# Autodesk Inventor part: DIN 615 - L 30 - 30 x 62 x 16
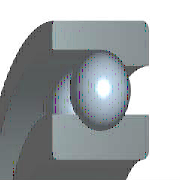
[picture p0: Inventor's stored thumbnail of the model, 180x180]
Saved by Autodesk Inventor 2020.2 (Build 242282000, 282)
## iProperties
Manager: www.cadconsulting.pl
Company: Fabian Stasiak CAD Consulting
Created: 2010-02
Part Number: DIN 615 - L 30 - 30 x 62 x 16
Material: Stal, miękka
Description: Łożysko kulkowe
Document SubType Name: Modeling
Standard: DIN 615
Designer: F.Stasiak
Standards Organization: DIN
Language: pl-PL
Size Designation: L 30 - 30 x 62 x 16
Categories: <MemberInstance><Categories><Category DisplayName="Części wałów" InternalName="7f7aeb1f-a693-4053-b835-cee3144e0d98" Mnemonic="SHFT"><Category DisplayName="Łoży
Density: 1 g/cm^3
Appearance: Metal-Stal
IsCustomPart: 0
Author: F.Stasiak
Subject: Zbiór ćwiczeń. Autodesk Inventor 2020. Kurs podstawowy
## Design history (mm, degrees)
sketch "Sketch" dims "d4" = 9.28 (= DDB)
  geometry: L1 (3.36, 23)-(12.64, 23); L2 (4.288, 20.216)-(0, 20.216); L3 (11.712, 20.216)-(16, 20.216); L4 (8, 27.64)-(0, 27.64); L5 (0, 31)-(16, 31); L6 (0, 15)-(16, 15); L7 (16, 15)-(16, 20.216); L8 (11.712, 25.784)-(16, 25.784); L9 (16, 25.784)-(16, 31); L10 (8, 23)-(8, 27.64); L11 (8, 23)-(8, 18.36); L12 (-3.2, 0)-(19.2, 0) reference; L13 (0, -2.6)-(0, 17.35) reference
  constraints: 22 end point, 5 parallel, 4 collinear, 4 point on line, 2 perpendicular, 1 horizontal, 1 midpoint, 9 other
  dimensions: "d10" = 30 diameter of L6 L12 (= WD); "d12" = 51.568 diameter of L8 L12 (= KAD1); "d14" = 46 diameter of L10.start L12 (= DDA); "d15" = 62 diameter of L5 L12 (= BD); "d16" = 40.432 diameter of L2 L12 (= KID1); "d17" = 16 distance between parallel lines of L13 L7 (= KB); "d18" = 8 distance from line of L13 L10.start (= 0.5 x KB)
revolve "Body" stored, may be unused: angle "d8" = 90 deg
fillet "Fillet1" dims "d0" = 1 (= KR1S), "d1" = 0.6 (= KR3S)
revolve "Ball" stored, may be unused: angle "d11" = 90 deg
pattern_circular "Balls" dims angle "d3" = 360 deg
body "Solid1"
other parameters: "WD" = 30 [user parameter; used in 2 equation terms], "BD" = 62 [user parameter; used in 2 equation terms], "KB" = 16 [user parameter; used in 2 equation terms], "KR1S" = 1 [user parameter; used in 1 equation term], "KR3S" = 0.6 [user parameter; used in 1 equation term], "KID1" = 40.432 [user parameter; used in 1 equation term], "KAD1" = 51.568 [user parameter; used in 2 equation terms], "DDA" = 46 [user parameter; used in 1 equation term], "DDB" = 9.28 [user parameter; used in 2 equation terms], "d5" = 0, "d6" = 0, "d7" = 0, "d9" = 0, "d19" = 0, "WR" = 15 (= 0.5 x WD) [user parameter], "BC" = 1.045e+07 [user parameter], "BC0" = 1950000 [user parameter], "DBB" = 55.28 [user parameter], "BR" = 31 (= 0.5 x BD) [user parameter], "BBA" = 0 [user parameter]
